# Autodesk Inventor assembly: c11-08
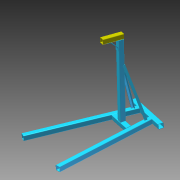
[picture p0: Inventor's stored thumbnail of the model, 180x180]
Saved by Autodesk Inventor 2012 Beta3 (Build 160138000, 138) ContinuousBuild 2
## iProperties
Created: 2011-01
Part Number: c11-08
Document SubType Name: Assembly
Designer: Beta-8540w
_SolveAssemblyDoc: Frame Generator Solve Assembly
_Version: 15.0.0
Author: Beta-8540w
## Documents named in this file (3)
- C:\Inventor 2012 Essentials\Assemblies\Chapter 11\c11-08.iam
- C:\Inventor 2012 Essentials\Parts\Chapter 11\c11-01.ipt
- C:\Inventor 2012 Essentials\Assemblies\Chapter 11\Frame\Frame c11-08.iam
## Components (2 placed, 2 different names)
1. c11-01:1
2. Frame c11-08:1 [sub-assembly]
